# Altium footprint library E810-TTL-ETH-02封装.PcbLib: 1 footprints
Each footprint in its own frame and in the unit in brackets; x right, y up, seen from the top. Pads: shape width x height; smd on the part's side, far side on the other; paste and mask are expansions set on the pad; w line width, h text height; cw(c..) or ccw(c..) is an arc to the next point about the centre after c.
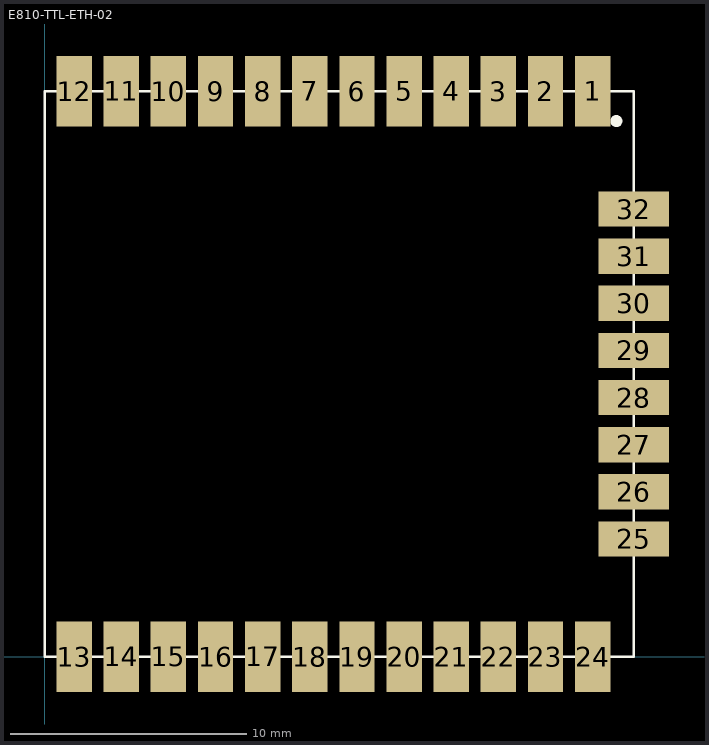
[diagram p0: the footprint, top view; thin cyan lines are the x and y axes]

## E810-TTL-ETH-02 [mm]
pads (32):
  rect 1.5x3 smd: 1(23.25,24) 2(21.25,24) 3(19.25,24) 4(17.25,24) 5(15.25,24) 6(13.25,24) 7(11.25,24) 8(9.25,24) 9(7.25,24) 10(5.25,24) 11(3.25,24) 12(1.25,24) 13(1.25,0) 14(3.25,0) 15(5.25,0) 16(7.25,0) 17(9.25,0) 18(11.25,0) 19(13.25,0) 20(15.25,0) 21(17.25,0) 22(19.25,0) 23(21.25,0) 24(23.25,0)
  rect 3x1.5 smd: 25(25,5) 26(25,7) 27(25,9) 28(25,11) 29(25,13) 30(25,15) 31(25,17) 32(25,19)
Top Overlay:
  circle w0.254: c24.257,22.733 r0.127
  lines w0.1: 0,0 25,0 25,24 0,24 0,0
Bottom Overlay:
  text "USBDP" at 22.85,18.8 h0.6
  text "USBDM" at 22.85,16.773 h0.6
  text "UR1_TX" at 22.85,12.819 h0.6
  text "UR1_RX" at 22.85,14.846 h0.6
  text "SPI1_SCK" at 22.85,6.737 h0.6
  text "SPI1_MOSI" at 22.85,8.764 h0.6
  text "SPI1_MISO" at 22.85,10.791 h0.6
  text "SPI1_SEL" at 22.84,5.83 h0.6
  text "G" at 1.01,4.22 h0.6
  text "RXD" at 8.956,1.74 h0.6
  text "VOUT" at 1,1.74 h0.6
  text "IO_RST" at 3.089,1.74 h0.6
  text "NC" at 4.978,1.74 h0.6
  text "TXD" at 6.967,1.74 h0.6
  text "NC" at 10.945,1.74 h0.6
  text "NC" at 12.935,1.74 h0.6
  text "NC" at 14.924,1.74 h0.6
  text "NC" at 16.913,1.74 h0.6
  text "LINKLED" at 18.902,1.74 h0.6
  text "SPDLED" at 20.891,1.74 h0.6
  text "GND" at 22.88,1.74 h0.6
  text "D" at 1.01,5.5 h0.6
  text "C" at 1,6.75 h0.6
  text "R" at 1,8.02 h0.6
  text "V" at 1.03,9.22 h0.6
  text "GND" at 1.05,20.01 h0.6
  text "VCC" at 3.027,20.01 h0.6
  text "nRST" at 5.005,20.01 h0.6
  text "NC" at 6.982,20.01 h0.6
  text "LED1" at 8.959,20.01 h0.6
  text "NC" at 10.936,20.01 h0.6
  text "LED2" at 12.914,20.01 h0.6
  text "TX-" at 16.868,20.01 h0.6
  text "TX+" at 18.845,20.01 h0.6
  text "RX-" at 20.823,20.01 h0.6
  text "RX+" at 22.8,20.01 h0.6
  text "AVDD" at 14.871,19.99 h0.6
